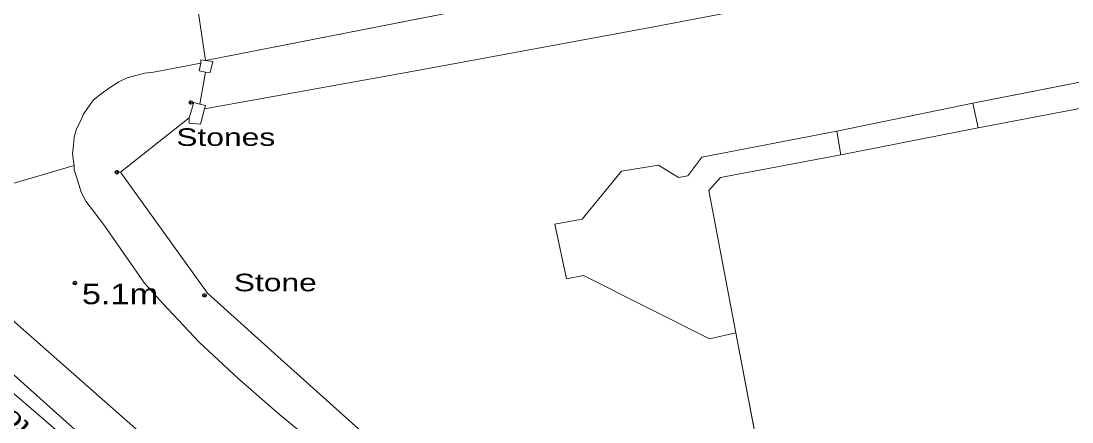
# Model space of a CAD drawing. Extents: x 528790 to 529292, y 179350 to 179856.
# Drawn here: x 529148.9 to 529238.4, y 179524.8 to 179559 of the extents above; entities that cross this region are included whole.
import ezdxf

# ---------------------------------------------------------------- set-up
doc = ezdxf.new("R2010")
doc.units = 0
doc.header["$LTSCALE"] = 0.6
doc.header["$PDMODE"] = 32
doc.header["$PDSIZE"] = 0.3
doc.layers.add('1', color=7, linetype='Continuous', lineweight=13)
doc.layers.add('2', color=7, linetype='Continuous', lineweight=13)
doc.layers.add('3', color=7, linetype='Continuous')
doc.layers.add('5', color=7, linetype='Continuous')

msp = doc.modelspace()

# ---------------------------------------------------------------- linework, layer by layer
at = {"layer": '1'}
for points in [[(529246.48, 179571.7), (529242.93, 179588.92), (529242.55, 179587.7), (529242.2, 179586.9), (529241.8, 179586.25), (529241.25, 179585.6), (529240.8, 179585), (529240.2, 179584.4), (529239.929, 179584.192), (529238.9, 179583.4), (529238.15, 179582.9), (529237.4, 179582.6), (529236.6, 179582.3), (529163.2, 179568.25), (529162.75, 179568.05), (529163.652, 179562), (529164.6, 179555.64)], [(529290.22, 179575.267), (529290.22, 179580.282), (529272.27, 179576.76), (529246.48, 179571.7), (529164.6, 179555.64), (529165.2, 179555.55), (529165, 179554.6), (529164.6, 179554.65), (529164.1, 179551.9), (529164.6, 179551.8), (529164.5, 179551.5), (529182.8, 179554.8), (529202.8, 179558.5), (529257.2, 179568.9), (529264.35, 179570.4), (529266.7, 179570.9), (529283, 179573.95)], [(529164.6, 179554.65), (529165, 179554.6), (529165.2, 179555.55), (529164.6, 179555.64), (529164.2, 179555.7), (529164.2, 179555.4), (529164.05, 179554.75)], [(529164.1, 179551.9), (529163.6, 179552.05), (529163.2, 179550.75), (529163.2, 179550.3), (529164.15, 179550.2), (529164.5, 179551.5), (529164.6, 179551.8)], [(529231.2, 179521.3), (529246.2, 179524.1), (529247.25, 179525.9), (529242.5, 179550.7), (529241.05, 179551.9), (529230.45, 179549.9), (529218.75, 179547.6), (529208.5, 179545.65), (529207.5, 179544.55), (529209.8, 179532.4), (529212.15, 179520.05), (529212.4, 179518.65), (529213.5, 179518.05), (529214.748, 179518.273), (529217.4, 179518.75), (529218.844, 179519.016), (529228.8, 179520.85)], [(529218.75, 179547.6), (529230.45, 179549.9), (529230, 179552), (529218.4, 179549.6)], [(529209.8, 179532.4), (529207.5, 179544.55), (529208.5, 179545.65), (529218.75, 179547.6), (529218.4, 179549.6), (529206.9, 179547.4), (529205.7, 179545.8), (529204.9, 179545.65), (529203.2, 179546.7), (529200.05, 179546.2), (529196.7, 179542.1), (529194.377, 179541.666), (529195.356, 179537.016), (529196.8, 179537.3), (529207.55, 179531.9)], [(529145.75, 179530.8), (529145, 179530.05), (529145.8, 179529.3), (529151.8, 179524.15), (529154.7, 179521.55), (529155.4, 179522.4), (529145.8, 179531)], [(529146.8, 179512.45), (529154.7, 179521.55), (529151.8, 179524.15), (529145.8, 179529.3), (529145, 179530.05), (529137, 179521.05), (529141.55, 179517.1), (529129.6, 179503.4), (529127.169, 179505.521), (529124.9, 179507.5), (529122.2, 179509.8), (529120.7, 179511.15), (529117.95, 179507.95), (529116.75, 179506.55), (529115.35, 179505), (529119.4, 179501.5), (529120.95, 179503.25), (529124.5, 179500), (529130.929, 179494.567), (529134.9, 179498.8), (529136, 179500)]]:
    msp.add_lwpolyline(points, close=True, dxfattribs=at)
for points in [[(529257.2, 179568.9), (529202.8, 179558.5), (529182.8, 179554.8), (529164.5, 179551.5), (529164.15, 179550.2), (529163.2, 179550.3), (529163.2, 179550.75), (529157.35, 179546.1), (529164.75, 179535.8), (529170.75, 179530.4), (529179.55, 179522.5)], [(529138, 179542.15), (529153.38, 179546.67), (529153.35, 179547.05), (529153.25, 179547.7), (529153.35, 179548.4), (529153.4, 179549.1), (529153.6, 179549.8), (529153.9, 179550.4), (529154.2, 179551.05), (529155, 179552.25), (529155.7, 179552.8), (529156.4, 179553.3), (529157.2, 179553.8), (529157.9, 179554.15), (529159.4, 179554.55), (529160.15, 179554.65), (529164.2, 179555.4), (529164.2, 179555.7), (529164.6, 179555.64), (529163.652, 179562)], [(529164.6, 179554.65), (529164.05, 179554.75), (529164.2, 179555.4), (529160.15, 179554.65), (529159.4, 179554.55), (529157.9, 179554.15), (529157.2, 179553.8), (529156.4, 179553.3), (529155.7, 179552.8), (529155, 179552.25), (529154.2, 179551.05), (529153.9, 179550.4), (529153.6, 179549.8), (529153.4, 179549.1), (529153.35, 179548.4), (529153.25, 179547.7), (529153.35, 179547.05), (529153.38, 179546.67), (529153.4, 179546.3), (529153.6, 179545.7), (529154, 179544.4), (529154.4, 179543.65), (529154.95, 179542.9), (529155.5, 179542.2), (529156, 179541.5), (529159.4, 179536.65), (529160.95, 179534.9), (529164.05, 179531.6), (529167.35, 179528.55), (529170.7, 179525.6), (529174.15, 179522.75)], [(529179.55, 179522.5), (529170.75, 179530.4), (529164.75, 179535.8), (529157.35, 179546.1), (529163.2, 179550.75), (529163.6, 179552.05), (529164.1, 179551.9), (529164.6, 179554.65)], [(529212.15, 179520.05), (529209.8, 179532.4), (529207.55, 179531.9), (529196.8, 179537.3), (529195.356, 179537.016), (529194.377, 179541.666), (529196.7, 179542.1), (529200.05, 179546.2), (529203.2, 179546.7), (529204.9, 179545.65), (529205.7, 179545.8), (529206.9, 179547.4), (529218.4, 179549.6), (529230, 179552), (529244.8, 179554.9)], [(529244.8, 179554.9), (529230, 179552), (529230.45, 179549.9), (529241.05, 179551.9)], [(529174.15, 179522.75), (529170.7, 179525.6), (529167.35, 179528.55), (529164.05, 179531.6), (529160.95, 179534.9), (529159.4, 179536.65), (529156, 179541.5), (529155.5, 179542.2), (529154.95, 179542.9), (529154.4, 179543.65), (529154, 179544.4), (529153.6, 179545.7), (529153.4, 179546.3), (529153.38, 179546.67), (529138, 179542.15)], [(529139.7, 179540.9), (529161.75, 179521.5), (529166.4, 179517.55), (529172.2, 179512.8), (529176.6, 179509.45), (529180.15, 179506.8), (529184.9, 179503.45), (529189.7, 179500), (529191.5, 179498.65), (529195.35, 179496.25), (529199.7, 179493.8), (529204.05, 179491.65), (529212.55, 179488.2), (529224, 179483.65), (529235.05, 179479.15), (529236, 179478.25), (529236.2, 179477.8), (529236.4, 179477.3), (529236.55, 179476.8), (529236.55, 179476.4), (529236.5, 179476), (529236.4, 179475.55), (529240, 179473.8)], [(529232.55, 179473.5), (529234, 179476.7), (529236.4, 179475.55), (529236.5, 179476), (529236.55, 179476.4), (529236.55, 179476.8), (529236.4, 179477.3), (529236.2, 179477.8), (529236, 179478.25), (529235.05, 179479.15), (529224, 179483.65), (529212.55, 179488.2), (529204.05, 179491.65), (529199.7, 179493.8), (529195.35, 179496.25), (529191.5, 179498.65), (529189.7, 179500), (529184.9, 179503.45), (529180.15, 179506.8), (529176.6, 179509.45), (529172.2, 179512.8), (529166.4, 179517.55), (529161.75, 179521.5), (529139.7, 179540.9)], [(529145.8, 179531), (529155.4, 179522.4)]]:
    msp.add_lwpolyline(points, dxfattribs=at)
at = {"layer": '2'}
for p, q in [((529164.6, 179555.64), (529246.48, 179571.7)), ((529164.6, 179554.65), (529164.1, 179551.9)), ((529244.8, 179554.9), (529230, 179552)), ((529218.4, 179549.6), (529230, 179552)), ((529230, 179552), (529230.45, 179549.9)), ((529218.75, 179547.6), (529230.45, 179549.9)), ((529218.75, 179547.6), (529218.4, 179549.6)), ((529138, 179542.15), (529153.38, 179546.67)), ((529212.15, 179520.05), (529209.8, 179532.4))]:
    msp.add_line(p, q, dxfattribs=at)
for points in [[(529164.5, 179551.5), (529182.8, 179554.8), (529202.8, 179558.5), (529257.2, 179568.9), (529264.35, 179570.4)], [(529162.75, 179568.05), (529163.652, 179562), (529164.6, 179555.64)], [(529153.38, 179546.67), (529153.35, 179547.05), (529153.25, 179547.7), (529153.35, 179548.4), (529153.4, 179549.1), (529153.6, 179549.8), (529153.9, 179550.4), (529154.2, 179551.05), (529155, 179552.25), (529155.7, 179552.8), (529156.4, 179553.3), (529157.2, 179553.8), (529157.9, 179554.15), (529159.4, 179554.55), (529160.15, 179554.65), (529164.2, 179555.4)], [(529164.6, 179554.65), (529164.05, 179554.75), (529164.2, 179555.4)], [(529164.2, 179555.4), (529164.2, 179555.7), (529164.6, 179555.64)], [(529164.6, 179555.64), (529165.2, 179555.55), (529165, 179554.6), (529164.6, 179554.65)], [(529163.2, 179550.75), (529163.6, 179552.05), (529164.1, 179551.9)], [(529164.1, 179551.9), (529164.6, 179551.8), (529164.5, 179551.5)], [(529230.45, 179549.9), (529241.05, 179551.9), (529242.5, 179550.7), (529247.25, 179525.9), (529246.2, 179524.1), (529231.2, 179521.3)], [(529163.2, 179550.75), (529163.2, 179550.3), (529164.15, 179550.2), (529164.5, 179551.5)], [(529179.55, 179522.5), (529170.75, 179530.4), (529164.75, 179535.8), (529157.35, 179546.1), (529163.2, 179550.75)], [(529209.8, 179532.4), (529207.55, 179531.9), (529196.8, 179537.3), (529195.356, 179537.016), (529194.377, 179541.666), (529196.7, 179542.1), (529200.05, 179546.2), (529203.2, 179546.7), (529204.9, 179545.65), (529205.7, 179545.8), (529206.9, 179547.4), (529218.4, 179549.6)], [(529209.8, 179532.4), (529207.5, 179544.55), (529208.5, 179545.65), (529218.75, 179547.6)], [(529216.757, 179496.282), (529209.4, 179500), (529202.15, 179503.95), (529198.8, 179505.75), (529195.5, 179507.55), (529192.2, 179509.45), (529183.15, 179515.8), (529178.6, 179519.25), (529174.15, 179522.75), (529170.7, 179525.6), (529167.35, 179528.55), (529164.05, 179531.6), (529160.95, 179534.9), (529159.4, 179536.65), (529156, 179541.5), (529155.5, 179542.2), (529154.95, 179542.9), (529154.4, 179543.65), (529154, 179544.4), (529153.6, 179545.7), (529153.4, 179546.3), (529153.38, 179546.67)], [(529138, 179542.15), (529139.7, 179540.9), (529161.75, 179521.5), (529166.4, 179517.55), (529172.2, 179512.8), (529176.6, 179509.45), (529180.15, 179506.8), (529184.9, 179503.45), (529189.7, 179500), (529191.5, 179498.65), (529195.35, 179496.25), (529199.7, 179493.8), (529204.05, 179491.65), (529212.55, 179488.2), (529224, 179483.65), (529235.05, 179479.15), (529236, 179478.25), (529236.2, 179477.8), (529236.4, 179477.3), (529236.55, 179476.8), (529236.55, 179476.4), (529236.5, 179476), (529236.4, 179475.55)], [(529145.75, 179530.8), (529145.8, 179531), (529155.4, 179522.4)], [(529154.7, 179521.55), (529151.8, 179524.15), (529145.8, 179529.3), (529145, 179530.05)]]:
    msp.add_lwpolyline(points, dxfattribs=at)
at = {"layer": '3'}
for p in [(529163.35, 179552.05), (529157.05, 179546.1), (529153.45, 179536.65), (529164.5, 179535.6)]:
    msp.add_point(p, dxfattribs=at)

# ---------------------------------------------------------------- texts
at = {"layer": '5'}
for s, height, width, p in [('Stones', 1.5, 1.35, (529162.1, 179548.35)), ('Stone', 1.5, 1.35, (529167, 179535.95)), ('5.1m', 1.75, 1.25, (529154.05, 179534.85))]:
    msp.add_text(s, height=height, dxfattribs=dict(at, width=width)).set_placement(p)
at = {"layer": '5', "width": 1.4}
msp.add_text('11 to 12', height=1.5, rotation=138, dxfattribs=at).set_placement((529152.65, 179521.92))

doc.saveas('drawing.dxf')
